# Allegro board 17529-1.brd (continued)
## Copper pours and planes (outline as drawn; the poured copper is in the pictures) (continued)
1D05V_CPU_SA on TOP: 91.63,104.41 91.41,104.63 89.53,104.63 87.9,106.26 87.9,109.96 87.78,110.08 86.61,110.08 86.44,110.26 86.44,117.14 86.59,117.3 87.99,117.3 88.67,116.61 88.67,115.06 89.14,114.6 90.36,114.6 90.71,114.24 92.25,114.24 92.37,114.11 92.37,113.57 93.1,112.84 93.1,110.96 92.33,110.19 92.33,108.31 91.93,107.92 91.93,107.64 92.11,107.46 92.11,107.28 91.91,107.08 91.91,106.72 92.03,106.6 92.03,106.29 91.93,106.19 91.93,105.83 92.06,105.71 92.06,105.38 91.91,105.22 91.91,104.89 92.11,104.69 92.11,104.51 92.01,104.41
1D05V_CPU_SA on BOTTOM: 114.81,52.83 114.05,53.59 114.05,62.87 115.06,63.88 126.59,63.88 127.89,62.59 127.89,57.56 127.2,56.87 125.32,56.87 124.82,56.36 124.82,54.84 124.71,54.74 123.83,54.74 121.92,52.83
1D05V_CPU_SA on L2VCC: 115.01,52.01 114.11,52.91 114.11,65.45 114.38,65.72 115.39,65.72 116.27,66.6 116.27,68.91 111.57,73.61 111.57,75.14 103.96,82.74 96.85,82.74 93.3,86.3 88.22,86.3 83.5,91.01 83.5,101.09 83.49,103.55 84.9,104.95 84.9,107 85.58,107 85.93,107 87.76,107 87.94,107.49 88.07,108.05 88.07,108.83 88.09,108.93 88.08,110.56 88.2,110.68 92.49,110.68 92.65,110.53 92.65,109.01 93.27,108.39 95.43,108.39 96.44,107.38 102.41,107.38 107.11,102.68 118.41,102.68 119.19,101.9 119.19,87.55 120.19,86.55 124.13,86.55 129.1,81.58 129.1,57.99 126.94,55.83 126.94,54.31 124.64,52.01
1D05V_LAN on TOP: 139.95,43.69 139.32,44.32 139.32,48.51 139.57,48.77 140.84,48.77 140.97,48.64 140.97,44.58 140.08,43.69 ; 2 cut-outs
1D05V_LAN on TOP: 138.86,42.6 138.79,42.67 138.05,42.67 136.27,44.45 136.27,45.31 136.3,45.34 136.3,48.03 136.47,48.21 137.59,48.21 137.79,48.01 137.79,44.96 139.27,43.48 139.27,42.62 139.24,42.6 ; 3 cut-outs
1D05V_LAN on TOP: 132.33,38.23 132.08,38.48 132.08,40.01 132.97,40.89 136.91,40.89 137.16,40.64 137.16,40.13 136.91,39.88 135.38,39.88 134.75,39.24 133.73,39.24 133.6,39.12 133.6,38.35 133.48,38.23 ; 2 cut-outs
1D05V_LAN on BOTTOM: 132.59,37.72 132.21,38.1 132.21,39.24 132.33,39.37 142.11,39.37 142.49,39.75 142.49,42.55 142.11,42.93 139.83,42.93 136.14,46.61 136.14,48.01 137.16,49.02 139.19,49.02 139.95,48.26 139.95,47.75 144.27,43.43 144.27,38.73 143.26,37.72
1D8V_PCH on TOP: 209.68,137.41 209.12,137.97 208.35,137.97 207.49,138.84 206.93,138.84 206.17,139.6 205.79,139.6 205,140.39 205,141 204.87,141.12 203.3,141.12 202.89,141.53 202.41,141.53 202.26,141.68 202.26,142.95 202.33,143.03 203.4,143.03 203.5,142.93 203.5,141.94 203.75,141.68 205.13,141.68 205.86,140.94 205.86,140.56 206.01,140.41 207.21,140.41 208.91,138.71 209.32,138.71 209.32,138.71 209.4,138.71 209.8,138.3 210.19,138.3 210.31,138.43 210.57,138.43 210.69,138.3 210.69,137.67 210.44,137.41
1D8V_PCH on BOTTOM: 202.72,141.94 202.16,142.49 202.16,143.81 202.29,143.94 203.45,143.94 203.56,143.84 203.56,142.09 203.4,141.94
1D24V_PCH on TOP: 203.94,143.18 203.81,143.31 203.81,143.31 203.65,143.46 203.65,144.06 204.01,144.42 204.83,144.42 205.28,143.97 205.28,143.64 205.31,143.61 205.31,143.33 205.16,143.18
2D5V_VPP_S3 on TOP: 145.29,166.37 145.03,166.62 145.03,168.02 144.15,168.91 144.15,178.69 144.65,179.2 144.65,180.21 144.4,180.47 144.4,182.12 145.54,183.26 152.91,183.26 153.16,183.51 153.16,185.42 154.18,186.44 154.18,188.09 154.31,188.21 155.96,188.21 156.21,187.96 156.21,177.8 152.78,174.37 152.78,167 152.15,166.37 ; 7 cut-outs
3D3V_AUD_S0 on TOP: 54.74,223.77 54.61,223.9 54.61,225.93 54.74,226.06 56.77,226.06 57.78,227.08 57.78,228.47 58.93,228.47 58.93,226.82 57.91,225.81 57.91,225.04 57.66,224.79 55.88,224.79 55.63,224.54 55.63,224.03 55.37,223.77 ; 3 cut-outs
3D3V_CARD_CON_S0 on TOP: 45.85,235.08 45.47,235.46 45.47,238.89 45.85,239.27 46.23,239.27 46.74,239.78 46.74,241.3 46.86,241.43 48.51,241.43 48.77,241.17 48.77,239.78 47.45,238.46 47.45,235.51 47.02,235.08 ; 4 cut-outs
3D3V_CARD_S0 on TOP: 43.89,235.05 43.21,235.74 43.21,236.37 43.64,236.8 45.11,236.8 45.21,236.7 45.21,235.1 45.16,235.05
3D3V_LAN on TOP: 145.41,37.41 145.29,37.54 145.29,38.71 143.89,40.11 143.89,40.51 144.02,40.64 146.18,40.64 146.56,40.26 146.56,37.54 146.43,37.41 ; 5 cut-outs
3D3V_LAN on TOP: 135,22.99 134.49,23.5 134.49,37.59 136.14,39.24 137.41,39.24 137.79,39.62 138.94,39.62 138.94,38.99 138.05,38.1 137.29,38.1 136.27,37.08 136.27,27.18 136.78,26.67 136.78,23.24 136.53,22.99 ; 3 cut-outs
3D3V_LAN on TOP: 139.19,43.56 137.92,44.83 137.92,48.26 136.78,49.4 133.48,49.4 133.22,49.66 133.22,50.67 133.35,50.8 138.18,50.8 139.19,49.78 139.19,44.32 139.57,43.94 139.57,43.81 139.32,43.56 ; 4 cut-outs
3D3V_LAN on BOTTOM: 134.62,34.04 134.49,34.16 134.49,35.43 134.62,35.56 143.64,35.56 144.91,36.83 144.91,42.93 140.21,47.62 140.21,48.13 139.06,49.28 136.02,49.28 135.76,49.53 135.76,51.94 136.02,52.2 138.94,52.2 143.26,47.88 144.15,47.88 147.07,44.96 147.07,36.58 144.53,34.04
3D3V_PCIVAUX_SB on TOP: 209.17,29.21 209.04,29.34 209.04,33.78 210.79,35.53 217.5,35.53 218.08,34.95 218.08,33.2 217.75,32.87 212.95,32.87 211.2,31.11 211.2,29.34 211.07,29.21 ; 6 cut-outs
3D3V_S0 on TOP: 197.12,78.3 196.29,79.12 195.83,79.12 195.71,79.25 195.71,80.14 195.83,80.26 196.6,80.26 196.72,80.39 196.72,81.03 196.85,81.15 198.37,81.15 198.5,81.03 198.5,80.09 198.07,79.65 198.07,78.49 197.88,78.3 ; 2 cut-outs
3D3V_S0 on TOP: 215.75,40.82 215.65,40.92 215.65,44.35 215.54,44.45 214.12,44.45 214,44.58 214,46.23 217.78,46.23 217.91,46.1 217.91,41.12 217.6,40.82
3D3V_S0 on TOP: 135.13,137.03 135,137.16 135,143.1 143.59,151.69 143.59,164.62 144.32,165.35 145.41,165.35 148.84,161.93 148.84,154.94 149.86,153.92 154.38,153.92 158.37,149.94 158.37,144.53 154.94,141.1 154.94,137.54 154.43,137.03 153.29,137.03 153.03,137.29 153.03,141.55 154.69,143.21 154.69,144.4 155.45,145.16 155.45,148.23 153.19,150.5 144.6,150.5 136.63,142.52 136.63,137.13 136.53,137.03 ; 7 cut-outs
3D3V_S0 on TOP: 205.74,67.69 205.41,68.02 203.48,68.02 203.43,68.07 203.33,68.07 203.07,67.82 202.44,67.82 202.06,68.2 202.06,69.47 202.18,69.6 209.68,69.6 210.57,68.71 210.57,67.97 210.45,67.86 209,67.86 208.66,68.2 208.03,68.2 207.52,67.69
3D3V_S0 on TOP: 99.06,182.75 95.12,186.69 95.12,196.47 91.69,199.9 91.69,207.26 93.47,207.26 93.98,207.77 103.12,207.77 104.91,209.56 106.44,209.56 108.39,211.52 110.43,211.52 122.3,223.39 126.49,223.39 127.25,222.63 127.25,213.36 116.97,203.07 99.69,203.07 98.17,201.55 98.17,188.59 100.71,186.06 145.36,186.06 145.54,185.88 145.54,183.59 144.7,182.75 ; 11 cut-outs
3D3V_S0 on TOP: 192.28,78.23 191.9,78.61 191.9,81.15 192.02,81.28 194.44,81.28 194.56,81.15 194.56,78.74 194.06,78.23 ; 1 cut-out
3D3V_S0 on TOP: 206.6,43.66 205.79,44.48 205.79,45.54 205.87,45.62 208.71,45.62 208.74,45.59 208.74,44.22 208.18,43.66
3D3V_S0 on BOTTOM: 233.43,214.25 223.27,224.41 191.39,224.41 189.29,222.31 189.29,220.66 188.59,219.96 180.72,219.96 178.05,222.63 174.24,222.63 172.47,220.85 172.47,216.66 172.09,216.28 162.18,216.28 160.27,218.19 139.32,218.19 137.03,220.47 135.33,220.47 133.6,222.2 130.94,222.2 128.93,224.21 127.23,224.21 126.64,223.62 126.64,221.41 126.47,221.23 123.77,221.23 121.36,223.65 121.36,231.98 121.92,232.54 151,232.54 158.37,225.17 162.25,223.14 165.86,223.14 175.26,232.54 228.35,232.54 238.38,222.5 238.38,215.65 236.98,214.25
3D3V_S0 on BOTTOM: 135.89,130.43 135,131.32 135,138.81 135.25,139.06 136.53,139.06 136.78,138.81 136.78,134.62 138.81,132.59 139.45,132.59 140.34,131.7 140.34,130.81 139.95,130.43
3D3V_S0 on BOTTOM: 151.38,128.65 151.13,128.91 151.13,130.81 151.76,131.44 151.76,138.56 152.15,138.94 154.69,138.94 154.81,138.81 154.81,129.16 154.31,128.65
3D3V_S0 on BOTTOM: 95.38,200.03 94.87,200.53 94.87,208.03 95.76,208.91 109.35,208.91 109.98,208.28 109.98,204.34 109.09,203.45 98.93,203.45 97.54,202.06 97.54,200.28 97.28,200.03
3D3V_S0 on L2VCC: 143.47,162.62 142.68,163.52 142.68,173.02 143.07,173.4 143.07,176.86 142.56,177.37 142.56,178.36 143.45,179.25 143.45,180.55 142.68,181.31 142.68,182.2 142.06,182.82 141.81,182.82 142.83,183.83 145.97,183.83 148.65,181.15 148.65,163.53 147.75,162.62
3D3V_S0 on L2VCC: outline of 119 points within 157.67,14.67 238.7,217.36 ; 2 cut-outs
3D3V_S0 on L3: 142.62,183.9 146.94,183.9 148.97,181.86 148.97,165.43 148.46,164.92 148.46,162.66 148.97,162.15 148.97,160.66 148.72,160.4 144.4,160.4 144.02,160.78 144.02,169.04 143.38,169.67 143.38,171.83 143,172.21 143,173.08 143.23,173.3 143.23,175.21 143,175.44 143,180.47 142.85,180.62 142.88,180.64 142.88,182.7 142.49,183.08 142.49,183.77
3D3V_S0 on L3: 235.2,109.47 235.08,109.35 221.23,109.35 220.98,109.6 220.98,126.49 221.87,127.38 223.65,127.38 224.03,127.76 224.03,129.29 225.68,130.94 225.68,132.97 228.47,135.76 228.47,142.11 227.97,142.62 227.97,149.48 227.08,150.37 227.08,158.75 228.6,160.27 234.82,160.27 235.2,159.89
3D3V_S5 on TOP: 234.23,170.78 233.9,171.11 233.9,173.36 233.93,173.4 233.93,174.75 234.31,175.13 235.97,175.13 236.22,174.88 236.22,171.14 235.85,170.78
3D3V_S5 on TOP: 194.02,99.23 193.55,99.69 193.55,100.58 193.09,101.04 192.56,101.04 192.51,101.09 192.48,101.09 192,101.57 192,105.11 192.05,105.16 193.17,105.16 193.29,105.03 193.29,104.65 193.98,103.96 193.98,103.38 194.11,103.25 196.6,103.25 196.82,103.48 197.97,103.48 198.09,103.35 198.09,102.59 198.32,102.36 198.32,102.06 198.02,101.75 196.49,101.75 196.09,101.35 196.09,99.23 ; 8 cut-outs
3D3V_S5 on TOP: 204.75,103.86 204.65,103.96 204.65,104.44 204.7,104.5 205.33,104.5 205.59,104.75 205.99,104.75 206.1,104.65 206.1,104.39 205.56,103.86
3D3V_S5 on TOP: 203.66,209.02 203.2,209.47 203.2,210.39 203.5,210.69 203.5,212.6 203.71,212.8 204.14,212.8 205.03,213.69 205.03,214.5 205.21,214.68 206.86,214.68 207.04,214.5 207.04,213.26 206.04,212.27 206.04,209.45 205.61,209.02 ; 6 cut-outs
3D3V_S5 on TOP: 150.37,195.71 150.24,195.83 150.24,197.23 150.37,197.36 152.65,197.36 153.42,198.12 153.42,202.95 154.31,203.84 155.32,203.84 155.83,203.33 155.83,196.22 155.32,195.71
3D3V_S5 on TOP: 85.47,203.33 84.2,204.6 84.2,216.79 85.27,216.79 86.11,215.95 86.11,214.38 86.74,213.74 89.2,213.74 89.59,214.12 89.59,214.43 89.94,214.78 90.81,214.78 90.83,214.76 90.83,209.65 91.44,209.04 91.44,203.33 ; 2 cut-outs
3D3V_S5 on TOP: 220.62,200.41 220.34,200.69 220.34,202.67 221.01,203.33 226.64,203.33 227.2,202.77 227.2,200.51 227.1,200.41
3D3V_S5 on TOP: 211.79,156.16 211.73,156.21 211.73,157.07 212.47,157.81 214.33,157.81 214.58,157.56 214.58,157.3 214.3,157.02 212.62,157.02 212.37,156.77 212.37,156.34 212.19,156.16
3D3V_S5 on TOP: 209.17,98.3 208.79,98.68 208.79,98.93 209.93,100.08 212.09,100.08 212.22,99.95 212.22,99.57 211.84,99.19 209.93,99.19 209.83,99.09 209.83,98.83 209.3,98.3
3D3V_S5 on TOP: 221.34,158.27 221.26,158.34 221.26,158.52 221.15,158.64 219.11,158.64 218.95,158.8 218.64,158.8 218.47,158.98 218.47,159.89 218.72,160.15 224.18,160.15 224.31,160.02 224.31,158.47 224.1,158.27 ; 5 cut-outs
3D3V_S5 on BOTTOM: 219.96,200.46 219.25,201.17 219.25,203.53 212.34,210.44 204.09,210.44 203.28,211.25 203.28,212.42 204.34,213.49 212.6,213.49 221.89,204.19 221.89,200.91 221.44,200.46
3D3V_S5 on BOTTOM: 224.23,200.03 224.08,200.18 224.08,202.72 224.43,203.07 226.16,203.07 226.34,202.9 226.34,200.13 226.24,200.03
3D3V_S5 on BOTTOM: 234.44,173.48 233.93,173.99 233.93,176.28 234.19,176.53 235.71,176.53 235.84,176.4 235.84,173.74 235.59,173.48
3D3V_S5 on L2VCC: 153.62,201.99 152.61,203.01 85.8,203.01 84.77,204.04 84.77,213.55 103.68,213.55 109.65,207.58 191.09,207.58 194.12,210.61 194.12,213.82 193.75,214.19 205.28,214.19 205.68,213.79 205.68,210.39 205.53,210.25 200.07,210.25 199.71,209.88 199.71,209.25 198.31,207.85 198.31,206.83 193.47,201.99
3D3V_SB on TOP: 201.68,79.78 201.17,80.29 201.17,81.2 201.24,81.28 203.58,81.28 203.84,81.03 203.84,80.01 203.61,79.78
3D3V_SB on TOP: 131.7,47.62 131.57,47.75 131.57,49.15 131.83,49.4 134.24,49.4 134.37,49.28 134.37,47.75 134.24,47.62
3D3V_SB on TOP: 205.66,164.34 205.56,164.44 205.56,165.13 205.79,165.35 207.04,165.35 207.11,165.43 207.11,166.12 207.31,166.32 207.7,166.32 207.72,166.34 207.72,167.11 207.77,167.16 208.43,167.16 208.71,166.88 208.71,165.2 208.81,165.1 209.63,165.1 209.68,165.05 209.68,164.41 209.6,164.34 ; 1 cut-out
3D3V_SB on TOP: 205.68,145.36 205.6,145.44 205.6,148.6 205.23,148.97 205.23,149.22 205.1,149.35 201.17,149.35 200.79,149.73 200.79,150.5 201.04,150.75 203.2,150.75 203.58,150.37 205.74,150.37 205.99,150.62 206.5,150.62 206.81,150.32 206.81,150.04 206.5,149.73 205.89,149.73 205.82,149.66 205.82,149.22 205.94,149.1 207.29,149.1 207.4,148.98 207.4,148.73 206.76,148.08 206.76,147.83 207.39,147.19 207.39,146.35 207.06,146.02 207.06,145.57 206.85,145.36
3D3V_SB on TOP: 206.5,140.94 205.71,141.73 205.71,141.81 205.59,141.94 205.16,141.94 204.95,142.14 204.95,142.47 205.64,143.15 205.92,143.15 206.35,143.59 207.09,143.59 207.29,143.38 207.29,143.08 207.3,143.07 207.3,142.86 207.72,142.44 207.72,141.17 207.49,140.94
3D3V_SB on TOP: 232.16,102.87 231.65,103.38 228.09,103.38 227.58,103.89 227.58,105.79 227.84,106.05 228.6,106.05 229.24,105.41 233.68,105.41 234.57,104.52 234.57,103 234.44,102.87
3D3V_SB on TOP: 212.47,27.94 212.34,28.07 212.34,28.83 212.22,28.96 211.58,28.96 211.46,29.08 211.46,30.23 211.58,30.35 214.12,30.35 214.25,30.23 214.25,28.19 214,27.94
3D3V_SB on TOP: 209.04,136.14 208.41,136.78 208.41,137.29 208.53,137.41 209.42,137.41 210.19,136.65 210.69,136.65 210.82,136.53 210.82,136.27 210.69,136.14
3D3V_SB on TOP: 94.64,211.38 94.44,211.58 92.18,211.58 92.18,214.76 92.23,214.81 93.01,214.81 93.45,214.38 97.03,214.38 101.98,219.33 109.98,219.33 119.25,228.6 132.72,228.6 133.6,227.71 133.6,225.04 132.72,224.16 121.03,224.16 109.47,212.6 100.61,212.6 99.39,211.38 ; 6 cut-outs
3D3V_SB on TOP: 216.18,148.95 216.08,149.05 216.08,149.89 216.48,150.29 218.31,150.29 218.54,150.06 218.54,149.1 218.39,148.95 ; 2 cut-outs
3D3V_SB on BOTTOM: 228.09,104.14 227.33,104.9 227.33,106.3 227.84,106.81 227.84,108.84 227.2,109.47 221.62,109.47 220.98,110.11 220.98,126.62 222.12,127.76 222.12,128.65 222.38,128.91 224.41,128.91 224.66,128.65 224.66,127.25 223.39,125.98 223.39,114.68 224.79,113.28 224.79,112.14 224.92,112.01 228.09,112.01 230,110.11 230,105.41 228.73,104.14
3D3V_SB on BOTTOM: 217.42,145.41 216.79,146.05 214.76,146.05 212.85,147.96 207.39,147.96 205.61,149.73 205.61,150.24 205.87,150.5 206.76,150.5 208.03,149.22 214.38,149.22 215.65,150.5 218.31,150.5 218.69,150.11 218.69,148.34 218.08,147.73 218.08,145.59 217.91,145.41
3D3V_SB on BOTTOM: 204.8,140.87 204.32,141.35 204.32,141.76 205.08,142.52 205.38,142.52 205.84,142.06 206.12,142.06 206.71,142.65 206.98,142.65 207.65,141.99 207.65,141.02 207.49,140.87 ; 1 cut-out
3D3V_SB on BOTTOM: 214.12,24.38 212.98,25.53 212.98,29.54 213.79,30.35 219.58,30.35 221.11,31.88 231.27,31.88 231.78,32.38 231.78,82.93 229.81,84.9 229.81,96.2 232.66,99.06 232.66,103.76 233.3,104.39 235.71,104.39 235.84,104.27 235.84,99.19 232.28,95.63 232.28,85.98 234.19,84.07 234.19,27.05 232.66,25.53 226.31,25.53 225.17,24.38
3D3V_SB on L2VCC: 205.56,78.93 205.3,79.2 205.3,79.42 205.93,80.06 205.93,81.2 206.06,81.33 206.06,83.25 207.06,83.25 207.07,83.23 207.07,81.84 207.69,81.22 212.14,81.22 212.28,81.07 212.28,80.47 212.01,80.2 210.61,80.2 209.34,78.93
3D3V_SB on L2VCC: 217.5,127.44 217.23,127.71 217.23,134.95 214.58,137.6 211.53,137.6 211.03,138.11 210.12,138.11 210.12,140.29 209.63,140.78 207.09,140.78 206.82,141.05 206.82,146.26 204.42,148.65 201.74,148.65 201.74,150.32 200.85,151.21 200.85,154.38 199.47,155.77 195.02,155.77 195.01,155.78 195.01,158.83 192.98,160.86 192.98,163.02 187.53,168.47 185.75,168.47 184.72,169.5 184.72,176.2 190.45,181.93 205.06,181.93 206.45,183.32 213.15,183.32 214.3,182.18 218.26,182.18 219.27,183.18 219.27,187.25 220.28,188.26 220.28,209.37 215.09,214.57 193.37,214.57 192.86,215.07 133.43,215.07 131.14,217.36 129.48,217.36 129.48,226.62 129.87,227.01 133.53,227.01 140.51,220.03 225.09,220.03 229.09,216.03 227.77,214.71 227.77,187.75 229.17,186.36 229.17,179.09 228.66,177.06 228.66,172.77 229.09,172.34 224.35,167.59 224.35,158.96 221.3,155.91 221.3,150.81 219.25,150.81 218.11,149.67 212.93,149.67 211.41,151.19 210.11,151.19 209.49,150.57 209.49,149.27 210.49,148.27 215.19,148.27 215.95,147.51 218.62,147.51 218.63,147.5 218.63,146.48 219.38,145.73 225.35,145.73 226,145.08 226,143.97 224.09,142.06 224.09,127.44 ; 2 cut-outs
3D3V_SPI on TOP: 189.99,198.88 189.74,199.14 189.74,201.8 190.75,202.82 190.75,209.3 191.13,209.68 192.35,209.68 192.66,209.37 192.66,208.41 192.51,208.25 192.51,206.6 191.9,205.99 191.9,203.33 192.86,202.36 192.86,201.5 192.66,201.29 190.91,201.29 190.63,201.02 190.63,199.01 190.5,198.88 ; 2 cut-outs
3D3V_WLAN_SB on TOP: 210.64,202.92 210.31,203.25 210.31,205.23 210.19,205.36 208.51,205.36 208.51,207.01 208.67,207.18 208.67,208.32 209.7,209.35 209.7,211.73 209.58,211.86 209.04,211.86 208.9,211.72 206.77,211.72 206.71,211.79 206.71,212.5 207.31,213.11 207.31,214.53 207.39,214.6 211.73,214.6 212.9,213.44 212.9,208.15 212.67,207.92 212.67,203.48 212.12,202.92 ; 9 cut-outs
3D3V_WLAN_SB on TOP: 209.88,186.87 209.27,187.48 208.58,187.48 208.41,187.66 208.41,188.62 208.46,188.67 210.06,188.67 210.26,188.87 210.26,189.08 210.3,189.12 210.32,189.12 210.32,189.24 210.44,189.36 211.73,189.36 211.94,189.15 211.94,187.05 211.76,186.87 ; 2 cut-outs
3D3V_WLAN_SB on BOTTOM: 209.04,186.82 208.51,187.35 208.51,204.72 208.89,205.1 210.9,205.1 211.99,204.01 211.99,193.09 211.43,192.53 211.43,187.5 211.05,187.12 211.05,187.1 210.77,186.82
LAN_CONN_CVT on TOP: 144.81,19.94 144.58,20.17 144.58,22.33 144.88,22.63 146,22.63 146.2,22.43 146.2,20.14 146,19.94 ; 4 cut-outs
PWR_1D0V on TOP: 226.49,115.42 225.45,116.46 225.45,126.72 225.4,126.77 225.12,126.77 224.82,127.08 224.82,127.84 225.03,128.05 232.83,128.05 237.01,123.88 237.01,120.14 236.75,119.89 232.33,119.89 232.31,119.86 232.13,119.86 231.78,119.51 231.78,116.18 231.01,115.42 ; 1 cut-out
PWR_1D0V on BOTTOM: 226.39,115.39 225.43,116.35 225.43,126.12 225.6,126.29 235.18,126.29 236.09,125.37 236.09,120.78 235.33,120.02 232.16,120.02 231.78,119.63 231.78,116.1 231.06,115.39
PWR_1D0V_PHASE on TOP: 228.68,128.65 228.35,128.98 228.35,132.46 229.78,133.89 229.78,142.15 229.87,142.24 229.87,145.92 230.07,146.13 231.24,146.13 231.44,145.92 231.44,145.16 231.29,145.01 231.29,142.14 232.7,140.73 232.7,135.07 233.3,134.47 233.3,133.27 235.89,130.68 235.89,128.8 235.74,128.65
PWR_1D0V_PHASE on BOTTOM: 228.68,128.63 228.35,128.96 228.35,132.59 230.76,135 232.66,135 235.99,131.67 235.99,128.83 235.79,128.63
PWR_1D0V_SNB on TOP: 228.22,142.49 228.19,142.52 228.19,143.23 228.09,143.33 227.23,143.33 227.13,143.43 227.13,145.29 227.3,145.47 229.12,145.47 229.36,145.22 229.36,142.52 229.34,142.49 ; 1 cut-out
PWR_1D0V_VCC on TOP: 230.08,146.78 230.05,146.81 230.05,148.16 230.19,148.3 230.72,148.3 230.86,148.44 230.86,149.45 230.91,149.5 233.05,149.5 233.15,149.6 233.23,149.6 233.31,149.68 233.31,150.67 233.33,150.69 233.59,150.69 233.61,150.67 233.61,149.42 233.18,148.99 233.18,148.97 232.8,148.59 232.8,148.2 231.38,146.78 ; 1 cut-out
PWR_2D5V on TOP: 154.56,188.47 154.31,188.72 154.31,189.1 154.05,189.36 152.4,189.36 152.27,189.48 152.27,190.37 151.89,190.75 149.61,190.75 149.61,192.66 150.24,193.29 155.57,193.29 155.83,193.04 155.83,191.9 156.21,191.52 156.21,188.72 155.96,188.47 ; 3 cut-outs
PWR_2D5V_VIN on TOP: 146.43,188.72 146.43,191.9 146.3,192.02 144.53,192.02 144.4,192.15 144.4,194.06 144.91,194.56 147.19,194.56 148.46,195.83 148.46,197.1 148.59,197.23 149.61,197.23 149.86,196.98 149.86,193.42 149.22,192.79 149.22,188.72
PWR_3D3V on TOP: 81.92,205.23 80.39,206.76 70.87,206.76 69.47,208.15 69.47,214 72.14,216.66 79.38,216.66 80.01,216.03 82.04,216.03 82.68,216.66 83.95,216.66 83.95,205.23 ; 2 cut-outs
PWR_3D3V on BOTTOM: 70.87,206.76 69.47,208.15 69.47,213.61 70.23,214.38 79.63,214.38 81.28,212.72 81.28,207.14 80.9,206.76
PWR_3V_PHASE2 on TOP: 56.52,200.53 56.52,206.12 59.61,206.12 60.2,206.71 60.2,208.28 60.45,208.53 60.45,212.95 60.48,212.98 68.07,212.98 68.58,212.47 68.58,204.6 64.52,200.53
PWR_3V_PHASE2 on BOTTOM: 56.77,200.53 56.64,200.66 56.64,205.99 56.77,206.12 59.44,206.12 60.2,206.88 60.2,208.28 60.45,208.53 60.45,213.11 60.83,213.49 67.77,213.49 68.58,212.67 68.58,204.6 64.52,200.53
PWR_3V_PHASE2 on L2VCC: 56.59,200.6 56.58,200.61 56.58,206.04 56.72,206.18 59.64,206.18 60.26,206.8 60.26,208.33 60.52,208.58 60.52,213.15 60.91,213.55 67.87,213.55 68.52,212.9 68.52,204.55 64.56,200.6
PWR_5V on TOP: 16.13,194.06 16.13,207.26 21.08,207.26 22.86,205.49 22.86,197.36 21.59,196.09 19.68,196.09 17.65,194.06 ; 1 cut-out
PWR_5V on BOTTOM: 16.71,194.34 16.38,194.67 16.38,206.96 16.69,207.26 21.08,207.26 22.86,205.49 22.86,197.36 21.59,196.09 19.68,196.09 17.93,194.34
PWR_5V3D3V_VIN on TOP: 32.26,199.9 32.26,205.49 36.83,205.49 38.25,206.91 40.41,206.91 42.55,209.04 42.55,213.03 43.03,213.51 52.45,213.51 52.58,213.39 54.38,213.39 54.86,213.87 54.86,214.63 54.99,214.76 60.2,214.76 60.2,209.17 58.19,209.17 57.68,208.66 50.42,208.66 49.91,208.15 49.91,205.49 46.23,201.8 38.1,201.8 37.72,201.42 37.72,200.03 37.59,199.9
PWR_5V_PHASE1 on TOP: 27.86,201.63 23.88,205.61 23.88,212.22 25.65,214 35.69,214 35.69,208.41 35.43,208.15 32.26,208.15 31.88,207.77 31.88,201.63
PWR_5V_PHASE1 on BOTTOM: 27.94,201.55 23.88,205.61 23.88,212.22 25.53,213.87 35.56,213.87 35.69,213.74 35.69,208.41 35.43,208.15 32.26,208.15 31.88,207.77 31.88,201.55
PWR_5V_PHASE1 on L2VCC: 27.89,201.61 23.94,205.56 23.94,212.27 25.61,213.93 35.62,213.93 35.62,208.36 35.35,208.09 32.18,208.09 31.81,207.72 31.81,201.61
PWR_12V_DUAL_1D0V on TOP: 236.22,135 235.84,135.38 235.84,136.96 235.74,137.06 234.19,137.06 233.97,136.84 233.97,136.83 233.93,136.8 233.93,135.47 233.87,135.4 233.23,135.4 233.15,135.48 233.15,139.3 233.17,139.32 233.17,140.72 234.34,140.72 234.54,140.92 234.54,145.9 234.85,146.2 237.31,146.2 237.44,146.08 237.44,142.67 238.53,141.58 238.53,139.42 238.3,139.19 237.87,139.19 237.49,138.81 237.49,135.23 237.26,135 ; 2 cut-outs
PWR_DDR4_LDOIN on TOP: 49.4,192.15 49.4,193.29 47.98,194.72 46.48,194.72 46.1,195.1 46.1,196.14 46.28,196.32 49.56,196.32 49.78,196.09 49.78,194.03 49.63,193.88 49.63,192.15
PWR_DDR4_LX on TOP: 66.5,185.62 66.42,185.7 66.42,191.26 69.6,191.26 70.36,192.02 70.36,197.74 70.48,197.87 77.72,197.87 78.11,197.49 78.11,191.9 71.83,185.62
PWR_DDR4_LX on BOTTOM: 66.85,186.11 66.55,186.41 66.55,191.13 66.67,191.26 69.47,191.26 70.36,192.15 70.36,197.99 77.6,197.99 78.09,197.5 78.09,191.25 72.95,186.11
PWR_DDR4_LX on L2VCC: 66.61,185.61 66.61,191.2 69.55,191.2 70.42,192.07 70.42,197.91 70.44,197.93 78.55,197.93 78.55,189.93 76.76,189.93 72.44,185.61
PWR_DDR4_UG1 on TOP: 70.61,198.5 70.61,199.39 70.99,199.77 70.99,201.96 71.17,202.13 74.02,202.13 74.37,201.78 74.37,201.02 74.22,200.86 72.47,200.86 72.14,200.53 72.14,198.88 71.75,198.5 ; 2 cut-outs
PWR_GT_BST2 on TOP: 13.59,123.57 13.46,123.7 13.46,124.71 13.59,124.84 15.47,124.84 15.72,124.59 16,124.59 16.01,124.6 16.24,124.6 16.26,124.59 16.26,123.83 16,123.57
PWR_GT_SW1 on TOP: 17.63,86.49 17.53,86.59 17.53,88.19 17.07,88.65 15.37,88.65 15.37,89.92 16.05,90.6 16.05,96.65 17.78,96.65 19.04,97.9 19.04,98.29 19.05,98.3 19.05,99.06 19.43,99.44 23.24,99.44 23.62,99.06 23.62,86.87 23.24,86.49
PWR_GT_SW1 on BOTTOM: 17.91,86.61 17.53,87 17.53,97.79 19.3,99.57 22.86,99.57 23.62,98.81 23.62,96.57 23.19,96.14 21.95,96.14 21.95,94.67 22.45,94.16 23.19,94.16 23.24,94.11 23.24,87.25 22.61,86.61
PWR_GT_SW1 on L2VCC: 17.99,86.68 17.72,86.95 17.72,87.96 16.97,88.71 15.57,88.71 15.56,88.72 15.56,89.71 16.19,90.35 16.19,96.44 16.33,96.58 17.48,96.58 18.86,97.97 18.86,99.24 19.13,99.5 23.04,99.5 23.43,99.11 23.43,86.95 23.16,86.68
PWR_GT_SW2 on TOP: 17.14,107.7 16.05,108.79 16.05,112.88 16.08,112.9 17.86,112.9 18.03,113.08 18.03,119.15 18.34,119.46 19.3,119.46 19.41,119.56 19.41,121.03 24.94,121.03 24.99,120.98 24.99,118.57 25.32,118.24 27.64,118.24 28.07,117.81 28.07,116.79 24.1,112.83 24.1,108.81 22.99,107.7 ; 2 cut-outs
PWR_GT_SW2 on BOTTOM: 17.14,107.7 16.13,108.71 16.13,112.78 16.51,113.16 17.91,113.16 18.03,113.28 18.03,119.76 19.18,120.9 26.16,120.9 28.07,119 28.07,116.69 23.88,112.5 23.88,110.92 23.22,110.26 22.12,110.26 21.89,110.03 21.89,108.92 22.05,108.76 22.48,108.76 22.85,108.39 22.85,107.94 22.61,107.7
PWR_GT_SW2 on L2VCC: 17.22,107.76 16.19,108.79 16.19,112.82 16.33,112.97 17.73,112.97 18.1,113.33 18.1,119.3 18.37,119.57 18.87,119.57 19.37,120.06 19.37,120.83 19.51,120.97 24.94,120.97 25.21,120.7 25.21,118.92 25.58,118.55 27.61,118.55 27.88,118.29 27.88,116.28 24.19,112.6 24.19,108.66 23.29,107.76
PWR_V_12V_CPU_S0_VSA on TOP: 110.49,39.88 110.49,44.65 110.69,44.86 115.47,44.86 115.7,45.09 116.92,45.09 117.17,45.34 117.17,46.69 117.22,46.74 117.91,46.74 117.93,46.71 117.93,41.53 117.81,41.4 116.2,41.4 116,41.2 116,39.98 115.9,39.88 ; 1 cut-out
PWR_VCCIO_VIN on TOP: 127.41,94.92 127.41,104.72 127.46,104.78 133.48,104.78 134.11,104.14 134.11,97.87 133.53,97.28 133.53,95.5 132.94,94.92
PWR_VCCSA_PHASE on TOP: 118.49,41.4 118.47,41.43 118.47,47.12 116.97,48.62 116.97,51.05 117.47,51.56 125.2,51.56 125.35,51.41 125.35,50.19 125.25,50.09 123.49,50.09 123.19,49.78 123.19,49.28 121.34,47.42 121.34,41.45 121.28,41.4
PWR_VCCSA_PHASE on BOTTOM: 118.57,41.45 118.47,41.55 118.47,46.99 116.97,48.49 116.97,51.05 117.47,51.56 125.2,51.56 125.37,51.38 125.37,50.19 125.27,50.09 123.93,50.09 121.31,47.47 121.31,41.76 121.01,41.45
PWR_VCORE_HG1_R on TOP: 42.13,49.15 42.13,51.02 42.55,51.44 45.59,51.44 45.59,50.67 43.94,50.67 43.56,50.29 43.56,49.15 ; 2 cut-outs
PWR_VCORE_HG2_R on TOP: 60.45,53.85 60.45,55.75 60.83,56.13 62.61,56.13 62.87,56.39 63.88,56.39 63.88,55.37 61.98,55.37 61.72,55.12 61.72,53.85 ; 2 cut-outs
PWR_VCORE_HG3_R on TOP: 78.74,56.9 78.71,56.92 78.71,58.78 79.12,59.18 82.17,59.18 82.17,58.42 80.52,58.42 80.14,58.04 80.14,56.9 ; 2 cut-outs
PWR_VCORE_HG4_R on TOP: 97.16,57.4 97.16,59.18 97.61,59.64 99.19,59.64 99.24,59.69 100.71,59.69 100.71,58.93 99.06,58.93 98.68,58.55 98.68,57.4 ; 2 cut-outs
PWR_VCORE_SNB1 on TOP: 33.43,64.54 33.35,64.62 33.35,66.17 33.66,66.47 35.56,66.47 35.74,66.29 35.74,64.69 35.59,64.54 ; 1 cut-out
PWR_VCORE_SW1 on TOP: 40.59,50.19 40.51,50.27 40.51,51.18 40.13,51.56 36.32,51.56 36.07,51.82 36.07,63.88 41.27,63.88 41.4,63.75 41.4,60.71 43.81,58.29 48.77,58.29 49.91,57.15 49.91,50.8 49.66,50.55 46.1,50.55 46.1,52.27 45.77,52.6 43.94,52.6 43.03,51.69 41.91,51.69 41.4,51.18 41.4,50.27 41.33,50.19 ; 2 cut-outs
PWR_VCORE_SW1 on BOTTOM: 46.1,50.55 46.1,52.2 45.85,52.45 44.7,52.45 43.81,51.56 36.32,51.56 36.07,51.82 36.07,62.87 36.32,63.12 38.86,63.12 45.72,56.26 46.35,56.26 46.61,56.52 46.61,57.53 46.86,57.78 49.28,57.78 49.91,57.15 49.91,50.8 49.66,50.55
PWR_VCORE_SW1 on L2VCC: 46.31,50.74 46.29,50.75 46.29,52.15 45.8,52.64 44.63,52.64 43.74,51.75 36.4,51.75 36.26,51.89 36.26,63.68 36.4,63.82 41.07,63.82 41.21,63.68 41.21,60.75 43.74,58.23 48.56,58.23 49.72,57.07 49.72,50.88 49.58,50.74
PWR_VCORE_SW2 on TOP: 58.93,54.74 58.8,54.86 58.8,55.88 58.42,56.26 54.61,56.26 54.36,56.52 54.36,68.58 59.56,68.58 59.69,68.45 59.69,63.12 59.94,62.87 67.18,62.87 68.2,61.85 68.2,55.5 67.94,55.24 64.39,55.24 64.39,57.02 64.14,57.28 62.87,57.28 62.36,56.77 61.72,56.77 61.34,56.39 60.2,56.39 59.69,55.88 59.69,54.86 59.56,54.74 ; 2 cut-outs
PWR_VCORE_SW2 on BOTTOM: 64.39,55.24 64.39,56.9 64.14,57.15 62.99,57.15 62.1,56.26 54.61,56.26 54.36,56.52 54.36,64.14 54.74,64.52 55.88,64.52 59.69,60.71 65.91,60.71 66.55,61.34 67.94,61.34 68.2,61.09 68.2,55.5 67.94,55.24
PWR_VCORE_SW2 on L2VCC: 64.34,55.44 64.33,55.45 64.33,56.97 64.09,57.21 62.91,57.21 62.15,56.45 54.69,56.45 54.42,56.72 54.42,68.25 54.56,68.39 59.36,68.39 59.5,68.25 59.5,63.17 59.87,62.8 67.1,62.8 68.26,61.64 68.26,55.58 68.12,55.44
PWR_VCORE_SW3 on TOP: 77.22,57.78 77.09,57.91 77.09,58.93 76.71,59.31 72.9,59.31 72.64,59.56 72.64,71.63 74.42,71.63 74.8,72.01 74.8,73.84 75.95,73.84 75.95,72.01 76.33,71.63 77.85,71.63 77.98,71.5 77.98,66.93 78.87,66.04 85.34,66.04 86.49,64.9 86.49,58.55 86.23,58.29 82.68,58.29 82.68,60.15 82.5,60.33 80.52,60.33 79.63,59.44 78.49,59.44 77.98,58.93 77.98,57.91 77.85,57.78 ; 2 cut-outs
PWR_VCORE_SW3 on BOTTOM: 82.68,58.29 82.68,59.94 82.42,60.2 81.28,60.2 80.39,59.31 72.9,59.31 72.64,59.56 72.64,67.18 73.03,67.56 76.07,67.56 78.74,64.9 82.3,64.9 82.8,64.39 83.82,64.39 84.07,64.64 84.07,65.02 84.2,65.15 86.23,65.15 86.49,64.9 86.49,58.55 86.23,58.29
PWR_VCORE_SW3 on L2VCC: 82.88,58.36 82.61,58.63 82.61,60.02 82.37,60.26 81.2,60.26 80.44,59.5 72.85,59.5 72.71,59.64 72.71,71.3 72.85,71.44 77.77,71.44 77.91,71.3 77.91,66.85 78.79,65.98 85.39,65.98 86.55,64.82 86.55,58.63 86.28,58.36
PWR_VCORE_SW4 on TOP: 95.76,58.29 95.63,58.42 95.63,59.44 95.25,59.82 91.44,59.82 91.19,60.07 91.19,72.14 92.96,72.14 93.34,72.52 93.34,74.32 94.61,74.32 94.61,72.52 95,72.14 96.39,72.14 96.52,72.01 96.52,68.96 98.93,66.55 103.89,66.55 105.03,65.41 105.03,59.05 104.78,58.8 101.22,58.8 101.22,60.58 100.99,60.81 99.03,60.81 98.2,59.97 97.05,59.97 96.52,59.44 96.52,58.42 96.39,58.29 ; 2 cut-outs
PWR_VCORE_SW4 on BOTTOM: 101.22,58.8 101.22,60.45 100.97,60.71 99.82,60.71 98.93,59.82 91.44,59.82 91.19,60.07 91.19,71.75 93.09,71.75 100.71,64.14 101.22,64.14 101.73,64.64 101.73,65.79 101.98,66.04 104.39,66.04 105.03,65.41 105.03,59.05 104.78,58.8
PWR_VCORE_SW4 on L2VCC: 101.42,58.86 101.28,59.01 101.28,60.4 100.92,60.77 99.87,60.77 98.98,59.88 91.39,59.88 91.25,60.02 91.25,72.07 92.92,72.07 93.41,72.57 93.41,74.36 94.55,74.36 94.55,72.57 95.04,72.07 96.31,72.07 96.46,71.93 96.46,69.01 98.98,66.48 103.93,66.48 105.09,65.33 105.09,59.26 104.7,58.86
PWR_VDDQ on TOP: 81.53,189.74 81.41,189.87 79.76,189.87 79.65,189.76 77.65,189.76 77.6,189.81 77.6,190.35 78.87,191.62 78.87,198.37 78.99,198.5 91.44,198.5 92.33,197.61 92.33,189.99 92.08,189.74 ; 2 cut-outs
PWR_VDDQ on BOTTOM: 79.12,189.87 78.87,190.12 78.87,198.37 78.99,198.5 91.44,198.5 92.33,197.61 92.33,190.37 91.82,189.87
PWR_VDDQ on L2VCC: 78.93,189.93 78.93,198.04 79.33,198.44 91.36,198.44 92.27,197.53 92.27,190.45 91.74,189.93
PWR_VDDQ_VIN on TOP: 57.66,193.8 57.38,194.08 57.38,197.82 57.56,197.99 62.99,197.99 64.64,199.64 69.85,199.64 69.98,199.52 69.98,194.44 69.72,194.18 64.52,194.18 64.14,193.8 ; 2 cut-outs
PWR_VTT on TOP: 44.83,190.5 44.32,191.01 44.32,194.31 44.07,194.56 44.07,196.09 45.72,196.09 45.72,195.07 46.35,194.44 48.01,194.44 49.23,193.22 49.23,192.15 49.02,192.15 48.39,192.79 48.13,192.79 47.75,192.41 47.75,191.72 47.9,191.57 48.77,191.57 48.77,191.34 47.9,191.34 47.83,191.26 46.74,191.26 45.97,190.5
SD_RCOMP on TOP: 213.11,129.41 212.85,129.67 212.85,130.18 213.33,130.66 213.51,130.66 213.69,130.84 213.69,131.37 213.39,131.67 212.93,131.67 211.48,133.12 211.48,133.5 211.73,133.76 212.12,133.76 212.32,133.55 212.32,133.12 212.7,132.74 214.17,132.74 214.53,132.38 214.53,130.45 214.52,130.44 214.52,130.42 213.51,129.41 ; 1 cut-out
SD_RCOMP on BOTTOM: 212.25,132.34 212.12,132.47 212.12,135.14 212.38,135.39 212.76,135.39 212.88,135.26 212.88,132.6 212.63,132.34
V_CPU_ST_PLL on TOP: 92.71,108.58 92.46,108.84 92.46,109.22 92.84,109.6 93.85,109.6 94.04,109.42 94.27,109.42 94.39,109.54 94.39,109.8 94.52,109.92 95.16,109.92 95.28,109.8 95.28,108.84 95.03,108.58

Small or netless copper shapes (teardrops, artwork), in the pictures only: 9 on TOP, 9 on BOTTOM, 1 on L3

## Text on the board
Ref Des/Silkscreen Top: OPERATION | FUNCTION | JUMPER | 1-2 SHORT : ME DISABLE | Service Mode | 1-2 OPEN : DEFAULT | 3-4 SHORT : DEFAULT | JMP1 | PW   CLR | 3-4 OPEN : PASSWORD RESET | 5-6 SHORT : RTC_CMOS RESET | CMOS   CLR | 5-6 OPEN : DEFAULT | PWR_SW | HDD_LED | 2 | 1 | 4 | 3 | APS_DEBUG | LPC_DEBUG | 5 | 6 | AUDIO2 | Card_Reader | HDMI | VGA | AUDIO1 | SSUSB_F | USB_R | NIC_USB | F3301:1.1A/6V | F5901:1.1A/6V | X3101:25MHZ | X1801:24MHZ | EG0720 | X1802:32.768KHZ | 17529-1 | H7MRM | MADE IN TAIWAN
User.18: T
User.27: AGND | 3D3V_S0 | 12V_CPU | PWR_5V_PHASE1 | 0D675V_VTT_S0 | 12V_S5 | GND | PWR_VCORE_SW2 | PWR_3V_PHASE2 | PWR_DDR4_LX | PWR_VCORE_SW3 | 0D95V_CPU_VCCIO | PWR_VDDQ | PWR_VCORE_SW4 | 1D2V_SM_S3 | 1D05V_CPU_SA | 12V_S0 | 3D3V_S5 | 1V_PCH_SB | 3D3V_SB | 1D24V_PCH
User.36: ByImpedance:100.0_DP@_REF_L1=("4.0/12.0(L2)" "3.5/9.0(L2)")|Type="DP"|_REF_L4=("4.0/12.0(L3)" "3.5/9.0(L3)")|imp="100.0" | ByImpedance:32.0_SE@_REF_L1=("9.5(L2)")|Type="SE"|_REF_L4=("9.5(L3)")|_REF_L3=("9.0(L2/L4)")|imp="32.0" | ByImpedance:34.0_SE@_REF_L1=("9.0(L2)")|Type="SE"|_REF_L4=("9.0(L3)")|_REF_L3=("8.0(L2/L4)")|imp="34.0" | ByImpedance:35.0_SE@_REF_L1=("8.5(L2)")|Type="SE"|_REF_L4=("8.5(L3)")|_REF_L3=("7.5(L2/L4)")|imp="35.0" | ByImpedance:37.5_SE@_REF_L1=("7.5(L2)")|Type="SE"|_REF_L4=("7.5(L3)")|_REF_L3=("7.0(L2/L4)")|imp="37.5" | ByImpedance:39.0_SE@_REF_L1=("7.0(L2)")|Type="SE"|_REF_L4=("7.0(L3)")|_REF_L3=("6.5(L2/L4)")|imp="39.0" | ByImpedance:40.0_SE@_REF_L1=("6.5(L2)")|Type="SE"|_REF_L4=("6.5(L3)")|_REF_L3=("6.0(L2/L4)")|imp="40.0" | ByImpedance:42.0_SE@_REF_L1=("6.0(L2)")|Type="SE"|_REF_L4=("6.0(L3)")|_REF_L3=("5.5(L2/L4)")|imp="42.0" | ByImpedance:45.0_SE@_REF_L1=("5.0(L2)")|Type="SE"|_REF_L4=("5.0(L3)")|_REF_L3=("4.5(L2/L4)")|imp="45.0" | ByImpedance:50.0_SE@_REF_L1=("4.0(L2)")|Type="SE"|_REF_L4=("4.0(L3)")|_REF_L3=("4.0(L2/L4)")|imp="50.0" | ByImpedance:60.0_DP@_REF_L1=("9.0/5.0(L2)")|Type="DP"|_REF_L4=("9.0/5.0(L3)")|_REF_L3=("8.0/5.0(L2/L4)")|imp="60.0" | ByImpedance:62.0_DP@_REF_L1=("8.5/5.0(L2)")|Type="DP"|_REF_L4=("8.5/5.0(L3)")|_REF_L3=("7.5/5.0(L2/L4)")|imp="62.0" | ByImpedance:65.0_DP@_REF_L1=("8.0/5.0(L2)")|Type="DP"|_REF_L4=("8.0/5.0(L3)")|_REF_L3=("7.0/5.5(L2/L4)")|imp="65.0" | ByImpedance:68.0_DP@_REF_L1=("6.5/4.0(L2)" "7.5/6.0(L2)")|Type="DP"|_REF_L4=("6.5/4.0(L3)" "7.5/6.0(L3)")|_REF_L3=("6.5/6.0(L2/L4)")|imp="68.0" | ByImpedance:70.0_DP@_REF_L1=("7.0/5.0(L2)")|Type="DP"|_REF_L4=("7.0/5.0(L3)")|_REF_L3=("6.0/5.0(L2/L4)")|imp="70.0" | ByImpedance:72.0_DP@_REF_L1=("7.0/7.0(L2)")|Type="DP"|_REF_L4=("7.0/7.0(L3)")|_REF_L3=("5.5/5.0(L2/L4)")|imp="72.0" | ByImpedance:80.0_DP@_REF_L1=("6.0/9.0(L2)" "4.5/4.0(L2)" "5.0/5.0(L2)")|Type="DP"|_REF_L4=("5.0/5.0(L3)" "6.0/9.0(L3)" "4.5/4.0(L3)")|_REF_L3=("4.5/6.0(L2/L4)")|imp="80.0" | ByImpedance:85.0_DP@_REF_L1=("5.0/7.0(L2)" "4.0/4.5(L2)")|Type="DP"|_REF_L4=("5.0/7.0(L3)" "4.0/4.5(L3)")|_REF_L3=("4.0/6.0(L2/L4)")|imp="85.0" | ByImpedance:90.0_DP@_REF_L1=("4.0/6.0(L2)")|Type="DP"|_REF_L4=("4.0/6.0(L3)")|_REF_L3=("4.0/9.0(L2/L4)")|imp="90.0" | ByImpedance:95.0_DP@_REF_L1=("4.0/8.0(L2)" "3.5/6.0(L2)")|Type="DP"|_REF_L4=("3.5/6.0(L3)" "4.0/8.0(L3)")|imp="95.0" | LayerIndex:nil | Source:4-1.6-8i.xls | artWorks:("_REF_L4" "_REF_L1" "_REF_L3") | gtImpOutlineUsed:BOARD GEOMETRY/PANEL_OUTLINE
User.37: Board Accuracy Check,Feb 02 15:25:47 2018,Passed | Dummy-Static-No Shape On Layer Check,Feb 02 15:25:47 2018,Passed | Split Plane Check,Feb 02 15:25:46 2018,Passed
User.42: This gerber is just for your reference to find the DP impedance traces in layer L1. | DP IMPEDANCE TABLE: L1 | * - Denotes that this Impedance | is NOT used | IMP(Ohm) | *60.0 | 62.0 | *65.0 | 68.0 | *68.0 | *70.0 | *72.0 | *80.0 | *85.0 | 85.0 | *90.0 | *95.0 | 100.0 | *100.0 | WIDTH(mils) | 9.0/5.0 | 8.5/5.0 | 8.0/5.0 | 6.5/4.0 | 7.5/6.0 | 7.0/5.0 | 7.0/7.0 | 6.0/9.0 | 4.5/4.0 | 5.0/5.0 | 5.0/7.0 | 4.0/4.5 | 4.0/6.0 | 4.0/8.0 | 3.5/6.0 | 4.0/12.0 | 3.5/9.0 | TYPE | DP | Ref. Plane | L2
User.44: This gerber is just for your reference to find the SE impedance traces in layer L1. | SE IMPEDANCE TABLE: L1 | * - Denotes that this Impedance | is NOT used | IMP(Ohm) | *32.0 | *34.0 | 35.0 | *37.5 | *39.0 | 40.0 | *42.0 | *45.0 | 50.0 | WIDTH(mils) | 9.5 | 9.0 | 8.5 | 7.5 | 7.0 | 6.5 | 6.0 | 5.0 | 4.0 | TYPE | SE | Ref. Plane | L2
User.45: Note:Refer to DRILL layer for ELLIPSE drill direction | FIGURE | SIZE | 10.0 | 16.0 | 20.0 | 25.0 | 26.0 | 28.0 | 29.0 | 30.0 | 36.0 | 37.0 | 39.0 | 40.0 | 41.0 | 52.0 | 54.0 | 56.0 | 64.0 | 91.0 | 109.0 | 126.0 | 46.0 | 48.0 | 50.0 | 65.0 | 67.0 | 86.0 | 93.0 | 97.0 | 119.0 | 150.0 | 158.0 | 166.0 | 189.0 | 197.0 | 48.0x24.0 | 63.0x36.0 | 91.0x32.0 | 95.0x36.0 | 97.0x48.0 | DRILL CHART: TOP to BOTTOM | ALL UNITS ARE IN MILS | PLATED | NON-PLATED | QTY | 4000 | 1078 | 64 | 21 | 576 | 22 | 236 | 7 | 14 | 16 | 52 | 31 | 147 | 6 | 8 | 12 | 1 | 2 | 4 | 3 | This gerber is just for your reference to find the DP impedance traces in layer L3. | This gerber is just for your reference to find the DP impedance traces in layer L4. | This gerber is just for your reference to find the SE impedance traces in layer L3. | This gerber is just for your reference to find the SE impedance traces in layer L4. | DP IMPEDANCE TABLE: L3 | DP IMPEDANCE TABLE: L4 | SE IMPEDANCE TABLE: L3 | SE IMPEDANCE TABLE: L4 | * - Denotes that this Impedance | is NOT used | Model | Eagle MT | Gambit MLK MT - ECO : | PCB_NO | 17529 | Eagle MT/Eagle Light - ECO : | VER. | 939799 | Layer | DRILL | L1 | L2VCC | TMASK | TPLACE | TSILK | TSMD | 939788 | Designer | BRUCE WU | Date | 02/02/2018 | IMP(Ohm) | *32.0 | *60.0 | *34.0 | *62.0 | 62.0 | *35.0 | *65.0 | 35.0 | *37.5 | *68.0 | *39.0 | 70.0 | *40.0 | *70.0 | *72.0 | *42.0 | *80.0 | *45.0 | *85.0 | *90.0 | 85.0 | *95.0 | *100.0 | WIDTH(mils) | 9.0 | 9.5 | 8.0 | 7.5 | 8.5 | 7.0 | 6.5 | 6.0 | 5.5 | 4.5 | 5.0 | 4.0 | 9.0/5.0 | 8.5/5.0 | 8.0/5.0 | 6.5/4.0 | 7.5/6.0 | 7.0/5.0 | 7.0/7.0 | 5.0/5.0 | 6.0/9.0 | 4.5/4.0 | 5.0/7.0 | 4.0/4.5 | 4.0/6.0 | 3.5/6.0 | 4.0/8.0 | 4.0/12.0 | 3.5/9.0 | 7.5/5.0 | 7.0/5.5 | 6.5/6.0 | 6.0/5.0 | 5.5/5.0 | 4.5/6.0 | 4.0/9.0 | TYPE | SE | DP | Ref. Plane | L2/L4 | L3 | BMASK | BPLACE | BSILK | BSMD | L4
